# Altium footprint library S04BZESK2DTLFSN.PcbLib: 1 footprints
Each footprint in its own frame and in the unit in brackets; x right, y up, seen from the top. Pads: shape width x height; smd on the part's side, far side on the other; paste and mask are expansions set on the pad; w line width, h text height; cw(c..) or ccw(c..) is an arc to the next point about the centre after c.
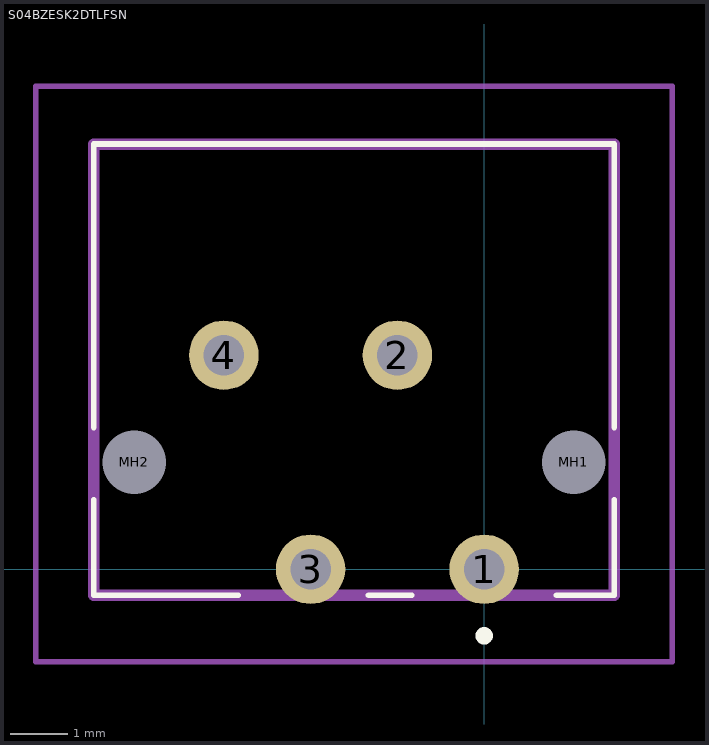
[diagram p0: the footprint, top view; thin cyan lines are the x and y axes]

## S04BZESK2DTLFSN [mm]
pads (6):
  round 1.2 hole 0.7: 1(0,0) 2(-1.5,3.7) 3(-3,0) 4(-4.5,3.7)
  round 0.55 hole 1.1 unplated: MH1(1.55,1.85) MH2(-6.05,1.85)
Top Overlay:
  lines w0.1: -6.75,-0.45 -4.25,-0.45 ; -6.75,-0.45 -6.75,-0.45 ; -6.75,-0.45 -4.25,-0.45 ; -6.75,-0.45 -6.75,-0.45 ; -6.75,-0.45 -6.75,1.2 ; -6.75,-0.45 -6.75,1.2 ; -6.75,1.2 -6.75,1.2 ; -6.75,2.45 -6.75,2.45 ; -6.75,2.45 -6.75,7.35 ; -6.75,2.45 -6.75,7.35 ; -6.75,7.35 -6.75,7.35 ; -6.75,7.35 2.25,7.35 ; -6.75,7.35 2.25,7.35 ; -6.75,7.35 -6.75,7.35 ; -4.25,-0.45 -4.25,-0.45 ; -2,-0.45 -1.25,-0.45 ; -2,-0.45 -2,-0.45 ; -2,-0.45 -1.25,-0.45 ; -1.25,-0.45 -1.25,-0.45 ; 1.25,-0.45 2.25,-0.45 ; 1.25,-0.45 1.25,-0.45 ; 1.25,-0.45 2.25,-0.45 ; 2.25,-0.45 2.25,1.2 ; 2.25,-0.45 2.25,-0.45 ; 2.25,-0.45 2.25,1.2 ; 2.25,-0.45 2.25,-0.45 ; 2.25,1.2 2.25,1.2 ; 2.25,2.45 2.25,7.35 ; 2.25,2.45 2.25,2.45 ; 2.25,2.45 2.25,7.35 ; 2.25,7.35 2.25,7.35 ; 2.25,7.35 2.25,7.35
  lines w0.2: 0,-1.2 cw(c0,-1.15) 0,-1.1 ; 0,-1.2 0,-1.2 ; 0,-1.2 ccw(c0,-1.15) 0,-1.1 ; 0,-1.2 cw(c0,-1.15) 0,-1.1 ; 0,-1.1 0,-1.1 ; 0,-1.1 0,-1.1
Mechanical 15:
  lines w0.2: -6.75,-0.45 2.25,-0.45 2.25,7.35 -6.75,7.35 -6.75,-0.45
Mechanical 20:
  lines w0.1: -7.75,-1.6 3.25,-1.6 3.25,8.35 -7.75,8.35 -7.75,-1.6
